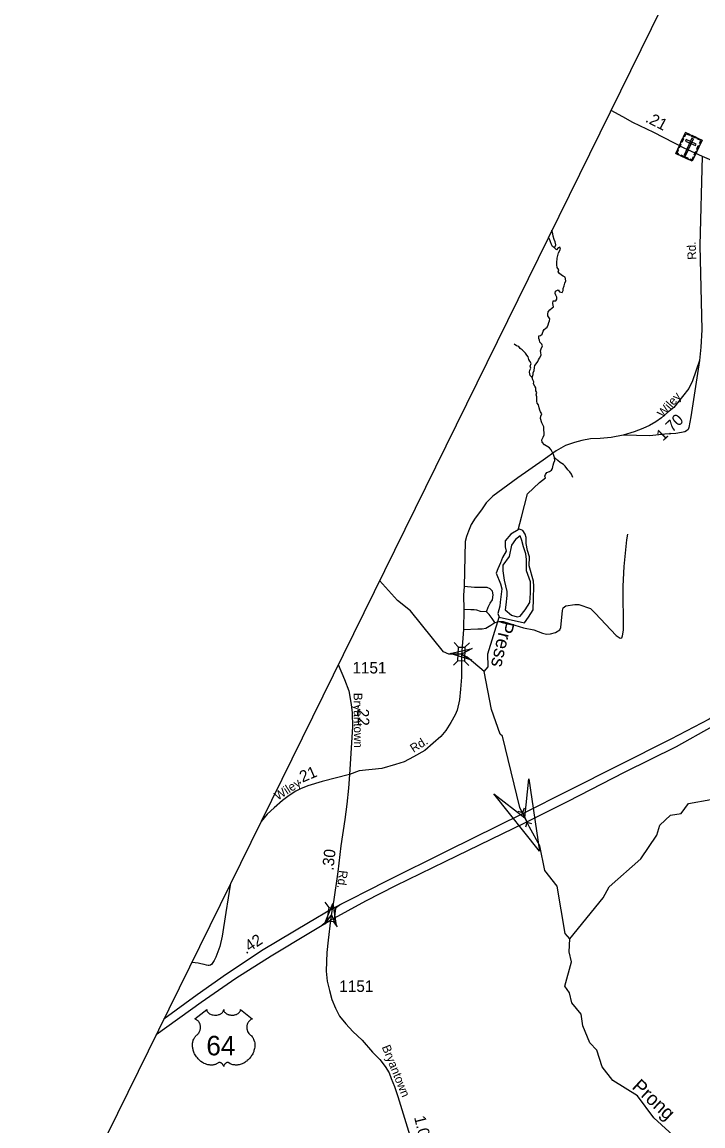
# Model space of a CAD drawing. Extents: x 2220236 to 2384410, y 720751 to 894131.
# Drawn here: x 2230421 to 2237843, y 775846 to 787885 of the extents above; entities that cross this region are included whole.
import ezdxf

# ---------------------------------------------------------------- set-up
doc = ezdxf.new("R2010")
doc.units = 0
for name, color, linetype in [('Exist Boundary Political CountyLine', 7, 'Continuous'), ('Exist Cultural Cemetery CELL', 7, 'Continuous'), ('Exist Hydrographic Buffer Line', 7, 'Continuous'), ('Exist Hydrographic Creek Single Shore', 7, 'Continuous'), ('Exist Hydrographic Creek Single Shore Label', 7, 'Continuous'), ('Exist Hydrographic Misc Water Feature', 7, 'Continuous'), ('Exist Hydrographic Pond Over 1500 Sq Ft', 7, 'Continuous'), ('Exist Road Non-System Type 51', 7, 'Continuous'), ('Exist Road Primary US Divided Attributed', 7, 'Continuous'), ('Exist Road Primary US Mileage Hundredths English Label', 7, 'Continuous'), ('Exist Road Primary US Shield CELL', 7, 'Continuous'), ('Exist Road Primary US Shield Number Label', 7, 'Continuous'), ('Exist Road Secondary Mileage Hundredths English Label', 7, 'Continuous'), ('Exist Road Secondary Structure Culvert Attributed CELL', 7, 'Continuous'), ('Exist Road Secondary Structure Culvert CELL', 7, 'Continuous'), ('Exist Road Secondary Structure Standard Bridge Attributed CELL', 7, 'Continuous'), ('Exist Road Secondary Structure Standard Bridge CELL', 7, 'Continuous'), ('Exist Road Secondary Type 51 Attributed', 7, 'Continuous'), ('Exist Road Secondary Type 51 Label', 7, 'Continuous'), ('Exist Road Secondary Type 51 Number Label', 7, 'Continuous')]:
    doc.layers.add(name, color=color, linetype=linetype)

msp = doc.modelspace()

# ---------------------------------------------------------------- linework, layer by layer
at = {"layer": 'Exist Boundary Political CountyLine'}
msp.add_lwpolyline([(2293118, 894131), (2291904, 891776), (2258822, 829665), (2255410, 823324), (2242089, 797599), (2231460, 775981), (2225011, 762953), (2220576, 753519)], dxfattribs=at)
at = {"layer": 'Exist Cultural Cemetery CELL'}
for points in [[(2237653, 786682), (2237834, 786598), (2237727, 786367), (2237547, 786451)], [(2237604, 786575), (2237622, 786615), (2237633, 786610), (2237614, 786571)], [(2237635, 786643), (2237646, 786638), (2237659, 786667), (2237696, 786650), (2237700, 786660), (2237653, 786682)], [(2237740, 786610), (2237723, 786617), (2237638, 786433), (2237655, 786426)], [(2237721, 786651), (2237768, 786629), (2237763, 786619), (2237716, 786641)], [(2237816, 786559), (2237806, 786564), (2237819, 786593), (2237782, 786610), (2237787, 786620), (2237834, 786598)], [(2237577, 786437), (2237581, 786447), (2237562, 786457), (2237578, 786493), (2237568, 786498), (2237547, 786451)], [(2237576, 786514), (2237594, 786554), (2237604, 786549), (2237586, 786510)], [(2237662, 786603), (2237654, 786586), (2237761, 786537), (2237769, 786554)], [(2237775, 786498), (2237793, 786537), (2237804, 786532), (2237785, 786493)], [(2237604, 786437), (2237681, 786402), (2237676, 786391), (2237599, 786427)], [(2237697, 786381), (2237702, 786392), (2237722, 786382), (2237739, 786419), (2237749, 786414), (2237727, 786367)], [(2237747, 786438), (2237766, 786477), (2237776, 786472), (2237758, 786433)]]:
    msp.add_lwpolyline(points, close=True, dxfattribs=at)
at = {"layer": 'Exist Hydrographic Buffer Line'}
msp.add_lwpolyline([(2235800, 782240), (2235756, 782179), (2235730, 782058), (2235661, 781962), (2235661, 781901), (2235678, 781797), (2235704, 781676), (2235704, 781632), (2235696, 781528), (2235687, 781476), (2235756, 781415), (2235817, 781398), (2235852, 781407), (2235904, 781476), (2235956, 781554), (2235964, 781658), (2235964, 781780), (2235921, 781901), (2235921, 782023), (2235912, 782084), (2235886, 782162), (2235869, 782231), (2235852, 782283), (2235800, 782240)], dxfattribs=at)
at = {"layer": 'Exist Hydrographic Creek Single Shore'}
for points in [[(2236224, 785421), (2236204, 785436), (2236194, 785458), (2236183, 785487), (2236175, 785510), (2236159, 785538)], [(2236224, 785421), (2236238, 785456), (2236234, 785487), (2236222, 785514), (2236212, 785551), (2236206, 785577), (2236197, 785616)], [(2235983, 784010), (2235994, 784041), (2235993, 784061), (2236005, 784084), (2236006, 784116), (2236011, 784141), (2236027, 784156), (2236042, 784184), (2236049, 784202), (2236062, 784221), (2236062, 784221), (2236079, 784251), (2236076, 784282), (2236074, 784301), (2236081, 784321), (2236081, 784321), (2236094, 784353), (2236088, 784372), (2236067, 784394), (2236061, 784414), (2236054, 784435), (2236054, 784435), (2236055, 784463), (2236074, 784468), (2236091, 784480), (2236091, 784480), (2236100, 784513), (2236113, 784531), (2236132, 784545), (2236145, 784558), (2236157, 784582), (2236162, 784609), (2236171, 784628), (2236174, 784647), (2236174, 784647), (2236154, 784682), (2236152, 784701), (2236156, 784725), (2236156, 784725), (2236174, 784745), (2236174, 784745), (2236198, 784769), (2236216, 784781), (2236216, 784781), (2236206, 784817), (2236209, 784844), (2236209, 784844), (2236241, 784844), (2236251, 784863), (2236250, 784885), (2236238, 784905), (2236231, 784925), (2236236, 784949), (2236236, 784949), (2236267, 784963), (2236280, 784942), (2236307, 784937), (2236321, 784956), (2236319, 784980), (2236329, 785009), (2236339, 785037), (2236348, 785063), (2236348, 785063), (2236341, 785102), (2236321, 785114), (2236302, 785126), (2236278, 785144), (2236266, 785162), (2236271, 785184), (2236271, 785184), (2236256, 785209), (2236252, 785237), (2236252, 785260), (2236252, 785260), (2236254, 785311), (2236262, 785338), (2236269, 785367), (2236292, 785407), (2236292, 785407), (2236284, 785429), (2236267, 785421), (2236248, 785402), (2236248, 785402), (2236224, 785421)], [(2235967, 784111), (2235960, 784133), (2235960, 784133), (2235971, 784163), (2235957, 784187), (2235947, 784204), (2235937, 784233), (2235925, 784253), (2235910, 784273), (2235889, 784295), (2235874, 784309), (2235850, 784324), (2235835, 784346), (2235811, 784355), (2235786, 784373)], [(2236226, 783135), (2236214, 783167), (2236189, 783218), (2236172, 783240), (2236116, 783276), (2236089, 783303), (2236088, 783329), (2236101, 783359), (2236111, 783383), (2236113, 783405), (2236110, 783437), (2236108, 783471), (2236088, 783514), (2236072, 783563), (2236076, 783588), (2236087, 783613), (2236072, 783633), (2236066, 783652), (2236058, 783677), (2236058, 783677), (2236051, 783710), (2236036, 783728), (2236033, 783750), (2236033, 783774), (2236033, 783798), (2236027, 783818), (2236031, 783845), (2236021, 783864), (2236021, 783864), (2236022, 783896), (2236012, 783915), (2235997, 783939), (2235999, 783962), (2235988, 783983), (2235983, 784010), (2235960, 784030), (2235954, 784068), (2235955, 784089), (2235967, 784111)], [(2235932, 782739), (2236062, 782865), (2236128, 782914), (2236119, 782933), (2236126, 782952), (2236143, 782972), (2236172, 782984), (2236192, 782997), (2236202, 783016), (2236202, 783016), (2236209, 783053), (2236219, 783079), (2236228, 783104), (2236226, 783135)], [(2236426, 782919), (2236411, 782955), (2236394, 782980), (2236370, 783002), (2236343, 783043), (2236323, 783060), (2236287, 783082), (2236263, 783103), (2236226, 783135)], [(2235828, 782349), (2235867, 782487), (2235932, 782739)], [(2235075, 780990), (2235016, 781015), (2234655, 781462), (2234512, 781576), (2234319, 781796)], [(2235460, 780802), (2235501, 780854), (2235500, 780995), (2235623, 781396)], [(2235460, 780802), (2235275, 780960), (2235211, 780993), (2235075, 780990)], [(2236392, 777887), (2236341, 777943), (2236254, 778460), (2236119, 778633), (2236067, 778900), (2235954, 779106), (2235903, 779208), (2235848, 779319), (2235657, 780096), (2235632, 780120), (2235538, 780387), (2235460, 780802)], [(2238513, 774428), (2238459, 774672), (2238190, 774937), (2238139, 775020), (2238078, 775375), (2237969, 775492), (2237559, 775704), (2237307, 775936), (2237130, 776176), (2236862, 776342), (2236744, 776489), (2236685, 776673), (2236609, 776754), (2236533, 776939), (2236515, 777064), (2236414, 777187), (2236388, 777296), (2236337, 777369), (2236410, 777637), (2236384, 777746), (2236392, 777887)]]:
    msp.add_lwpolyline(points, dxfattribs=at)
at = {"layer": 'Exist Hydrographic Misc Water Feature'}
msp.add_lwpolyline([(2236392, 777887), (2236754, 778332), (2236820, 778455), (2237167, 778759), (2237340, 779018), (2237373, 779126), (2237488, 779235), (2237605, 779252), (2237687, 779362), (2237928, 779406)], dxfattribs=at)
at = {"layer": 'Exist Hydrographic Pond Over 1500 Sq Ft'}
msp.add_lwpolyline([(2235607, 781433), (2235623, 781396), (2235897, 781333), (2235941, 781394), (2235993, 781476), (2235997, 781593), (2236001, 781732), (2235997, 781789), (2235949, 781954), (2235954, 782053), (2235932, 782123), (2235915, 782197), (2235915, 782262), (2235906, 782301), (2235880, 782340), (2235845, 782353), (2235828, 782349), (2235750, 782301), (2235689, 782227), (2235689, 782162), (2235698, 782114), (2235659, 782045), (2235637, 781988), (2235607, 781923), (2235589, 781875), (2235637, 781758), (2235650, 781702), (2235633, 781559), (2235628, 781515)], close=True, dxfattribs=at)
at = {"layer": 'Exist Road Non-System Type 51'}
for points in [[(2237806, 784195), (2237712, 783580), (2237691, 783463), (2237682, 783443), (2237665, 783427), (2237645, 783417), (2237611, 783410), (2237548, 783397), (2237427, 783390), (2237266, 783374), (2236973, 783380)], [(2235575, 781337), (2235621, 781348), (2235664, 781346), (2235746, 781322), (2235887, 781279), (2236000, 781257), (2236096, 781222), (2236139, 781211), (2236182, 781213), (2236235, 781229), (2236284, 781255), (2236295, 781281), (2236313, 781467), (2236321, 781498), (2236349, 781519), (2236446, 781532), (2236489, 781532), (2236617, 781489), (2236669, 781439), (2236899, 781194), (2236942, 781164), (2236959, 781170), (2236968, 781190), (2236976, 781253), (2236972, 781734), (2236986, 781949), (2237014, 782238), (2237024, 782299)], [(2235484, 781452), (2235501, 781504), (2235525, 781546), (2235549, 781582), (2235558, 781639), (2235549, 781680), (2235525, 781702), (2235491, 781719), (2235354, 781719), (2235239, 781728)], [(2235484, 781452), (2235419, 781457), (2235380, 781472), (2235350, 781474), (2235313, 781474), (2235237, 781478)], [(2235575, 781337), (2235545, 781381), (2235514, 781424), (2235484, 781452)], [(2235232, 781261), (2235391, 781266), (2235438, 781266), (2235478, 781276), (2235532, 781309), (2235575, 781337)], [(2232694, 778492), (2232642, 778173), (2232604, 777916), (2232577, 777803), (2232532, 777687), (2232516, 777651), (2232502, 777629), (2232491, 777612), (2232474, 777601), (2232460, 777595), (2232448, 777595), (2232431, 777599), (2232406, 777605), (2232371, 777614), (2232340, 777623), (2232307, 777625), (2232269, 777627)]]:
    msp.add_lwpolyline(points, dxfattribs=at)
at = {"layer": 'Exist Road Primary US Divided Attributed'}
for points in [[(2233785, 778089), (2234169, 778301), (2234495, 778469), (2235033, 778731), (2235909, 779156), (2236376, 779389), (2236990, 779703), (2237555, 779983), (2237945, 780201), (2238312, 780419), (2238590, 780604), (2238736, 780712), (2238908, 780847), (2239109, 781024), (2239323, 781217), (2239549, 781435), (2239906, 781823), (2240112, 782064), (2240353, 782340), (2240693, 782720), (2241328, 783439), (2241584, 783729)], [(2241510, 783780), (2241272, 783516), (2240633, 782793), (2240284, 782398), (2240043, 782122), (2239842, 781894), (2239486, 781496), (2239240, 781262), (2239066, 781107), (2238846, 780915), (2238697, 780793), (2238546, 780682), (2238277, 780500), (2237910, 780284), (2237495, 780064), (2236922, 779777), (2236380, 779505), (2235878, 779250), (2235058, 778847), (2234385, 778513), (2233803, 778213)], [(2233803, 778213), (2233545, 778062), (2233050, 777766), (2232649, 777500), (2232330, 777276), (2231965, 777009)], [(2231883, 776842), (2232375, 777196), (2232753, 777459), (2233136, 777701), (2233567, 777958), (2233785, 778089)]]:
    msp.add_lwpolyline(points, dxfattribs=at)
at = {"layer": 'Exist Road Primary US Shield CELL'}
msp.add_lwpolyline([(2232435, 777115), (2232435, 777110), (2232436, 777104), (2232437, 777101), (2232440, 777094), (2232445, 777087), (2232452, 777080), (2232460, 777073), (2232465, 777070), (2232474, 777065), (2232483, 777061), (2232495, 777058), (2232506, 777056), (2232518, 777054), (2232530, 777054), (2232544, 777055), (2232558, 777058), (2232565, 777060), (2232573, 777062), (2232580, 777065), (2232587, 777069), (2232593, 777073), (2232598, 777077), (2232605, 777083), (2232610, 777090), (2232613, 777094), (2232615, 777097), (2232617, 777105), (2232618, 777109), (2232619, 777116), (2232619, 777110), (2232620, 777106), (2232621, 777102), (2232622, 777099), (2232625, 777093), (2232628, 777088), (2232634, 777082), (2232637, 777078), (2232641, 777076), (2232649, 777070), (2232660, 777065), (2232665, 777062), (2232670, 777061), (2232676, 777059), (2232683, 777057), (2232690, 777056), (2232697, 777055), (2232704, 777054), (2232709, 777054), (2232716, 777054), (2232723, 777055), (2232729, 777055), (2232737, 777057), (2232742, 777058), (2232750, 777060), (2232757, 777062), (2232763, 777065), (2232771, 777069), (2232778, 777073), (2232782, 777077), (2232788, 777082), (2232793, 777088), (2232796, 777093), (2232799, 777098), (2232801, 777102), (2232802, 777108), (2232803, 777112), (2232803, 777116), (2232931, 777013), (2232928, 777012), (2232921, 777009), (2232916, 777006), (2232907, 776999), (2232903, 776996), (2232899, 776992), (2232896, 776989), (2232893, 776985), (2232889, 776980), (2232886, 776975), (2232882, 776969), (2232880, 776964), (2232876, 776954), (2232874, 776947), (2232873, 776942), (2232871, 776930), (2232871, 776925), (2232871, 776919), (2232871, 776914), (2232872, 776908), (2232873, 776902), (2232874, 776897), (2232875, 776891), (2232878, 776884), (2232880, 776877), (2232886, 776866), (2232894, 776855), (2232899, 776848), (2232905, 776843), (2232913, 776836), (2232917, 776832), (2232922, 776827), (2232930, 776818), (2232933, 776814), (2232936, 776809), (2232939, 776804), (2232942, 776798), (2232945, 776793), (2232949, 776782), (2232953, 776772), (2232954, 776766), (2232957, 776753), (2232958, 776747), (2232959, 776735), (2232959, 776720), (2232957, 776706), (2232955, 776689), (2232953, 776679), (2232949, 776668), (2232946, 776658), (2232940, 776643), (2232935, 776633), (2232928, 776620), (2232923, 776613), (2232918, 776605), (2232911, 776595), (2232903, 776585), (2232894, 776575), (2232886, 776567), (2232876, 776558), (2232870, 776553), (2232862, 776547), (2232850, 776539), (2232838, 776532), (2232828, 776527), (2232819, 776523), (2232808, 776519), (2232789, 776514), (2232782, 776512), (2232774, 776511), (2232766, 776510), (2232759, 776510), (2232749, 776510), (2232739, 776511), (2232729, 776512), (2232719, 776514), (2232709, 776517), (2232700, 776521), (2232690, 776525), (2232675, 776535), (2232670, 776538), (2232667, 776538), (2232661, 776539), (2232655, 776538), (2232649, 776535), (2232646, 776533), (2232641, 776530), (2232638, 776527), (2232633, 776523), (2232630, 776520), (2232628, 776517), (2232623, 776510), (2232622, 776506), (2232620, 776502), (2232619, 776496), (2232617, 776504), (2232614, 776509), (2232611, 776514), (2232609, 776518), (2232604, 776523), (2232600, 776527), (2232595, 776531), (2232590, 776534), (2232586, 776536), (2232582, 776537), (2232577, 776539), (2232574, 776539), (2232571, 776539), (2232566, 776538), (2232560, 776534), (2232555, 776530), (2232549, 776526), (2232542, 776522), (2232537, 776520), (2232530, 776517), (2232523, 776515), (2232515, 776513), (2232507, 776511), (2232500, 776510), (2232492, 776510), (2232485, 776509), (2232478, 776509), (2232471, 776510), (2232464, 776511), (2232454, 776512), (2232446, 776514), (2232437, 776516), (2232429, 776519), (2232419, 776522), (2232407, 776528), (2232399, 776532), (2232387, 776539), (2232371, 776549), (2232360, 776559), (2232352, 776566), (2232340, 776579), (2232332, 776587), (2232321, 776601), (2232314, 776612), (2232309, 776620), (2232302, 776632), (2232299, 776640), (2232294, 776651), (2232290, 776662), (2232287, 776672), (2232285, 776678), (2232283, 776689), (2232281, 776697), (2232280, 776708), (2232279, 776719), (2232279, 776729), (2232279, 776738), (2232280, 776748), (2232282, 776759), (2232284, 776768), (2232286, 776775), (2232288, 776783), (2232292, 776792), (2232296, 776800), (2232300, 776807), (2232305, 776815), (2232310, 776821), (2232317, 776828), (2232324, 776835), (2232330, 776840), (2232338, 776847), (2232341, 776852), (2232346, 776858), (2232350, 776863), (2232353, 776869), (2232357, 776876), (2232359, 776882), (2232362, 776890), (2232363, 776896), (2232365, 776904), (2232366, 776912), (2232366, 776921), (2232366, 776928), (2232365, 776937), (2232363, 776946), (2232361, 776953), (2232358, 776962), (2232355, 776968), (2232350, 776976), (2232345, 776984), (2232339, 776991), (2232334, 776996), (2232328, 777001), (2232323, 777004), (2232316, 777008), (2232310, 777011), (2232306, 777013)], close=True, dxfattribs=at)
at = {"layer": 'Exist Road Secondary Structure Culvert Attributed CELL'}
msp.add_lwpolyline([(2235945, 779633), (2236061, 778841), (2235565, 779468), (2235903, 779208)], close=True, dxfattribs=at)
at = {"layer": 'Exist Road Secondary Structure Culvert CELL'}
for p, q in [((2235827, 779278), (2235876, 779263)), ((2235894, 779310), (2235876, 779263)), ((2235876, 779263), (2235929, 779154)), ((2235912, 779107), (2235929, 779154)), ((2235978, 779139), (2235929, 779154))]:
    msp.add_line(p, q, dxfattribs=at)
at = {"layer": 'Exist Road Secondary Structure Standard Bridge Attributed CELL'}
for points in [[(2235323, 780927), (2235089, 780997), (2235326, 781053), (2235211, 780993)], [(2233719, 778045), (2233807, 778273), (2233844, 778032), (2233794, 778151)]]:
    msp.add_lwpolyline(points, close=True, dxfattribs=at)
at = {"layer": 'Exist Road Secondary Structure Standard Bridge CELL'}
for p, q in [((2235177, 781069), (2235130, 781119)), ((2235246, 781067), (2235297, 781115)), ((2235123, 780870), (2235173, 780918)), ((2235291, 780866), (2235244, 780916)), ((2233768, 778230), (2233726, 778285)), ((2233836, 778221), (2233891, 778263)), ((2233693, 778038), (2233748, 778080)), ((2233860, 778017), (2233818, 778071))]:
    msp.add_line(p, q, dxfattribs=at)
for points in [[(2235173, 780918), (2235177, 781069), (2235248, 781067), (2235244, 780916)], [(2233748, 778080), (2233768, 778230), (2233838, 778221), (2233818, 778071)]]:
    msp.add_lwpolyline(points, close=True, dxfattribs=at)
at = {"layer": 'Exist Road Secondary Type 51 Attributed'}
for points in [[(2236841, 786925), (2236967, 786854), (2237077, 786795), (2237303, 786683), (2237634, 786514), (2237835, 786424)], [(2237835, 786424), (2237811, 785448), (2237833, 784527), (2237821, 784341), (2237806, 784195), (2237728, 783972), (2237689, 783888), (2237620, 783800), (2237526, 783683), (2237455, 783624), (2237393, 783568), (2237330, 783525), (2237260, 783486), (2237188, 783454), (2237092, 783415), (2236973, 783380), (2236842, 783354), (2236724, 783345), (2236617, 783340), (2236525, 783322), (2236445, 783300), (2236346, 783268), (2236242, 783208), (2236102, 783107), (2235825, 782913), (2235552, 782714), (2235480, 782641), (2235428, 782565), (2235361, 782476), (2235317, 782407), (2235287, 782334), (2235265, 782276), (2235253, 782221), (2235239, 781728), (2235233, 781634), (2235237, 781478), (2235232, 781261), (2235211, 780981)], [(2237835, 786424), (2238164, 786280), (2238621, 786089), (2238738, 786043)], [(2235211, 780981), (2235211, 780739), (2235200, 780608), (2235191, 780494), (2235164, 780382), (2235143, 780328), (2235095, 780246), (2235040, 780159), (2234987, 780093), (2234902, 780019), (2234812, 779941), (2234687, 779871), (2234585, 779818), (2234493, 779788), (2234342, 779744), (2234095, 779718), (2233989, 779679)], [(2233868, 780879), (2233936, 780714), (2233982, 780592), (2234010, 780444), (2234018, 780350), (2234022, 780198), (2233989, 779679)], [(2233989, 779679), (2233693, 779602), (2233535, 779556), (2233457, 779523), (2233404, 779496), (2233332, 779450), (2233260, 779394), (2233168, 779316), (2233094, 779247), (2233027, 779168)], [(2233989, 779679), (2233978, 779530), (2233960, 779357), (2233941, 779189), (2233895, 778902), (2233863, 778619), (2233815, 778289), (2233803, 778213)], [(2233803, 778213), (2233785, 778089)], [(2233785, 778089), (2233757, 777871), (2233744, 777739), (2233740, 777639), (2233737, 777535), (2233748, 777424), (2233772, 777324), (2233799, 777226), (2233838, 777131), (2233883, 777045), (2233949, 776960), (2234028, 776876), (2234127, 776780), (2234243, 776651), (2234321, 776569), (2234379, 776494), (2234423, 776424), (2234445, 776363), (2234480, 776277), (2234517, 776168), (2234647, 775741)]]:
    msp.add_lwpolyline(points, dxfattribs=at)

# ---------------------------------------------------------------- texts
at = {"layer": 'Exist Hydrographic Creek Single Shore Label'}
for s, rotation, p in [('Press', 256.9738, (2235646, 781367)), ('Prong', 317.428, (2237060, 776261))]:
    msp.add_text(s, height=150, rotation=rotation, dxfattribs=at).set_placement(p)
at = {"layer": 'Exist Road Primary US Mileage Hundredths English Label'}
msp.add_text('.42', height=125, rotation=33.5523, dxfattribs=at).set_placement((2232862, 777716))
at = {"layer": 'Exist Road Primary US Shield Number Label'}
msp.add_text('64', height=212.5, dxfattribs=at).set_placement((2232430, 776616))
at = {"layer": 'Exist Road Secondary Mileage Hundredths English Label'}
for s, rotation, p in [('.21', 333.0015, (2237207, 786802)), ('1.70', 43.6591, (2237407, 783309)), ('.22', 271.9006, (2234075, 780439)), ('.21', 23.0018, (2233435, 779571)), ('.30', 83.3992, (2233814, 778627)), ('1.09', 284.0545, (2234693, 775941))]:
    msp.add_text(s, height=125, rotation=rotation, dxfattribs=at).set_placement(p)
at = {"layer": 'Exist Road Secondary Type 51 Label'}
for s, rotation, p in [('Rd.', 92.7959, (2237772, 785295)), ('Wiley', 48.7982, (2237407, 783564)), ('Bryantown', 270.4877, (2234035, 780569)), ('Rd.', 32.139, (2234688, 779914)), ('Wiley', 33.0072, (2233209, 779393)), ('Rd.', 263.192, (2233878, 778638)), ('Bryantown', 292.0442, (2234341, 776707))]:
    msp.add_text(s, height=95, rotation=rotation, dxfattribs=at).set_placement(p)
at = {"layer": 'Exist Road Secondary Type 51 Number Label'}
for p in [(2234022, 780781), (2233879, 777308)]:
    msp.add_text('1151', height=125, dxfattribs=at).set_placement(p)

doc.saveas('drawing.dxf')
